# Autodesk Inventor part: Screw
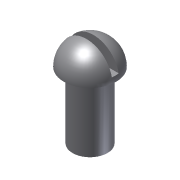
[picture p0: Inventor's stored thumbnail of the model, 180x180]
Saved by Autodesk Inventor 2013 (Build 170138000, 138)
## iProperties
Created: 2009-04
Part Number: Screw
Document SubType Name: Modeling
Designer: Sham
Density: 1 g/cm^3
Material: Generic
Author: Sham
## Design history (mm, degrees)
sketch "Sketch1"
  geometry: C1 r 10 at (0, 0)
  constraints: 1 centre point
  dimensions: "d0" = 20 diameter of C1
extrude "Extrusion1" new body sketch "Sketch1" distance "d1" = 38; taper "d2" = 0 deg
sketch "Sketch2"
  geometry: L1 (0, 38)-(-15, 38); L2 (-10, 38)-(10, 38) reference; L3 (0, 38)-(0, 53); A1 r 15 centre (0, 38) between (0, 53) and (-15, 38)
  constraints: 4 end point, 2 point on circle, 1 centre point, 1 collinear, 1 perpendicular
  dimensions: "d3" = 15 radius of A1
revolve "Revolution1" sketch "Sketch2" stored, may be unused: angle "d4" = 90 deg
sketch "Sketch3"
  geometry: L1 (2, 54)-(2, 41); L2 (2, 41)-(-2, 41); L3 (-2, 41)-(-2, 54); L4 (-2, 54)-(2, 54); L5 (15, 38)-(-15, 38) reference
  constraints: 8 end point, 2 parallel, 1 perpendicular, 1 vertical
  dimensions: "d5" = 3 distance between parallel lines of L5 L2; "d6" = 4 distance between parallel lines of L3 L1
extrude "Extrusion2" cut sketch "Sketch3" stored distance "d7" = 38; taper "d8" = 0 deg
body "Solid1"
